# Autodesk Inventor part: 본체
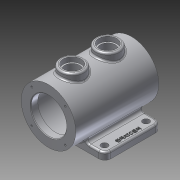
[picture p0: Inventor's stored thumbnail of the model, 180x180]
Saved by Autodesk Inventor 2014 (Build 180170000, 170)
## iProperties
Created: 2014-12
Part Number: 본체
Material: 알루미늄 6061
Document SubType Name: Modeling
Designer: Owner
Density: 2.71 g/cm^3
Appearance: 알루미늄 - 평지
Mass: 1293.91 g
Surface Area: 1040.15 cm^2
Volume: 477.456 cm^3
Author: Owner
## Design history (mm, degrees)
node "작업 평면1"
sketch "스케치3"
  geometry: C1 r 46 at (0, 0); 1 further point
  constraints: 1 centre point, 1 coincident
  dimensions: "d1" = 92 diameter of C1
extrude "돌출1" new body sketch "스케치3" stored distance "d2" = 140; taper "d3" = 0 deg
node "작업 평면2"
node "작업 평면5"
sketch "스케치6"
  geometry: L1 (46, 70)-(-46, 70) reference; L2 (-46, -70)-(46, -70) reference; L3 (-65, 55)-(65, 55); L4 (65, 55)-(65, -40); L5 (65, -40)-(-65, -40); L6 (-65, -40)-(-65, 55); 2 further points
  constraints: 8 end point, 2 parallel, 1 horizontal, 1 midpoint, 1 perpendicular, 1 vertical alignment
  dimensions: "d18" = 130 distance of L3.start L3.end; "d19" = 15 vertical distance of L3.end L1.start; "d20" = 95 distance of L3.end L4.end
extrude "돌출4" join sketch "스케치6" distance "d21" = 12; taper "d22" = 0 deg
node "작업 평면6"
sketch "스케치7"
  geometry: L1 (46, 70)-(-46, 70) reference; L2 (-46, -70)-(46, -70) reference; C1 r 20 at (0, 30); C2 r 20 at (0, -30); 1 further point
  constraints: 2 centre point, 2 vertical alignment
  dimensions: "d24" = 40 diameter of C1; "d25" = 40 diameter of C2; "d26" = 40 distance from line of L1 C1.centre; "d27" = 40 distance from line of L2 C2.centre
extrude "돌출5" join sketch "스케치7" stored distance "d28" = 12; taper "d29" = 0 deg
sketch "스케치8"
  geometry: C1 r 20 at (0, 0) reference; C2 r 20 at (0, -60) reference; C3 r 15 at (0, 0); C4 r 15 at (0, -60); 1 further point
  constraints: 2 centre point, 2 coincident
  dimensions: "d30" = 30 diameter of C3; "d31" = 30 diameter of C4
extrude "돌출6" cut sketch "스케치8" distance "d32" = 8; taper "d33" = 0 deg
sketch "스케치9"
  geometry: C1 r 15 at (0, 0) reference; C2 r 15 at (0, -60) reference; C3 r 12.5 at (0, 0); C4 r 12.5 at (0, -60); 1 further point
  constraints: 2 centre point, 2 coincident
  dimensions: "d34" = 25 diameter of C3; "d35" = 25 diameter of C4
sketch "스케치10"
  geometry: C1 r 46 at (0, 0) reference; C2 r 30 at (0, 0)
  constraints: 1 centre point, 1 coincident
  dimensions: "d36" = 60 diameter of C2
extrude "돌출7" cut sketch "스케치10" distance "d37" = 12; taper "d38" = 0 deg
sketch "스케치11"
  geometry: C1 r 30 at (0, 0) reference; C2 r 37.5 at (0, 0)
  constraints: 1 centre point, 1 coincident
  dimensions: "d39" = 75 diameter of C2
extrude "돌출8" cut sketch "스케치11" distance "d40" = 116; taper "d41" = 0 deg
sketch "스케치12"
  geometry: C1 r 46 at (0, 0) reference; C2 r 30 at (0, 0)
  constraints: 1 centre point, 1 coincident
  dimensions: "d42" = 60 diameter of C2
extrude "돌출9" cut sketch "스케치12" distance "d43" = 12; taper "d44" = 0 deg
extrude "돌출10" cut sketch "스케치9" stored distance "d45" = 12; taper "d46" = 0 deg
sketch "스케치13"
  geometry: L1 (0, 0)-(28.284, 28.284); L2 (0, 0)-(40, 0); C1 r 46 at (0, 0) reference; 1 further point
  constraints: 4 end point, 1 coincident, 1 equal length, 1 horizontal
  dimensions: "d47" = 40 distance of L1.start L1.end; "d48" = 45 deg angle of L2 L1
hole "구멍1" sketch "스케치13" at (28.284, 28.284) diameter "d49" = 3.242; stored, may be unused: countersink angle "d53" = 90 deg, drill point angle "d55" = 118 deg; dims "d50" = 8, "d51" = 4, "d52" = 2, "d54" = 10
sketch "스케치14"
  geometry: L1 (0, 0)-(28.284, 28.284); L2 (0, 0)-(40, 0); C1 r 46 at (0, 0) reference; 1 further point
  constraints: 4 end point, 1 coincident, 1 equal length, 1 horizontal
  dimensions: "d59" = 40 distance of L1.start L1.end; "d60" = 45 deg angle of L2 L1
hole "구멍2" sketch "스케치14" at (28.284, 28.284) diameter "d61" = 3.242; stored, may be unused: countersink angle "d65" = 90 deg, drill point angle "d67" = 118 deg; dims "d62" = 8, "d63" = 4, "d64" = 2, "d66" = 10
sketch "스케치15"
  geometry: L1 (65, -40)-(65, 55) reference; 3 further points
  constraints: 1 horizontal alignment, 1 midpoint, 1 other
  dimensions: "d71" = 8 distance of point (65, 7.5) point (57, 7.5)
feature "엠보싱1" sketch "스케치15" dims "d72" = 1, "d73" = 0
sketch "스케치16"
  geometry: L1 (65, -40)-(65, 55) reference; L2 (65, 55)-(25.923, 55) reference; 2 further points
  dimensions: "d74" = 12.5 distance from line of point (52, 42.5) L2; "d75" = 13 distance from line of L1 point (52, 42.5)
hole "구멍3" sketch "스케치16" at (52, 42.5) diameter "d76" = 11; stored, may be unused: countersink angle "d80" = 90 deg, drill point angle "d82" = 0 deg; dims "d77" = 8, "d78" = 4, "d79" = 2, "d81" = 10
fillet "모깎기1" dims "d86" = 10
fillet "모깎기2" dims "d87" = 5
fillet "모깎기3" dims "d88" = 3
chamfer "모따기1" distance "d89" = 1; stored, may be unused: second distance "d90" = 2, angle "d91" = 45 deg
fillet "모깎기4" dims "d92" = 3
fillet "모깎기5" dims "d93" = 3
fillet "모깎기6" dims "d94" = 3
node "솔리드1"
pattern_circular "원형 패턴1" dims angle "d57" = 360 deg
pattern_circular "원형 패턴2" dims angle "d69" = 360 deg
pattern_linear "직사각형 패턴1" dims "d85" = 70
mirror "대칭1"
node "투영된 루프3"
other parameters: "d0" = 0, "d4" = -106, "d23" = 56
